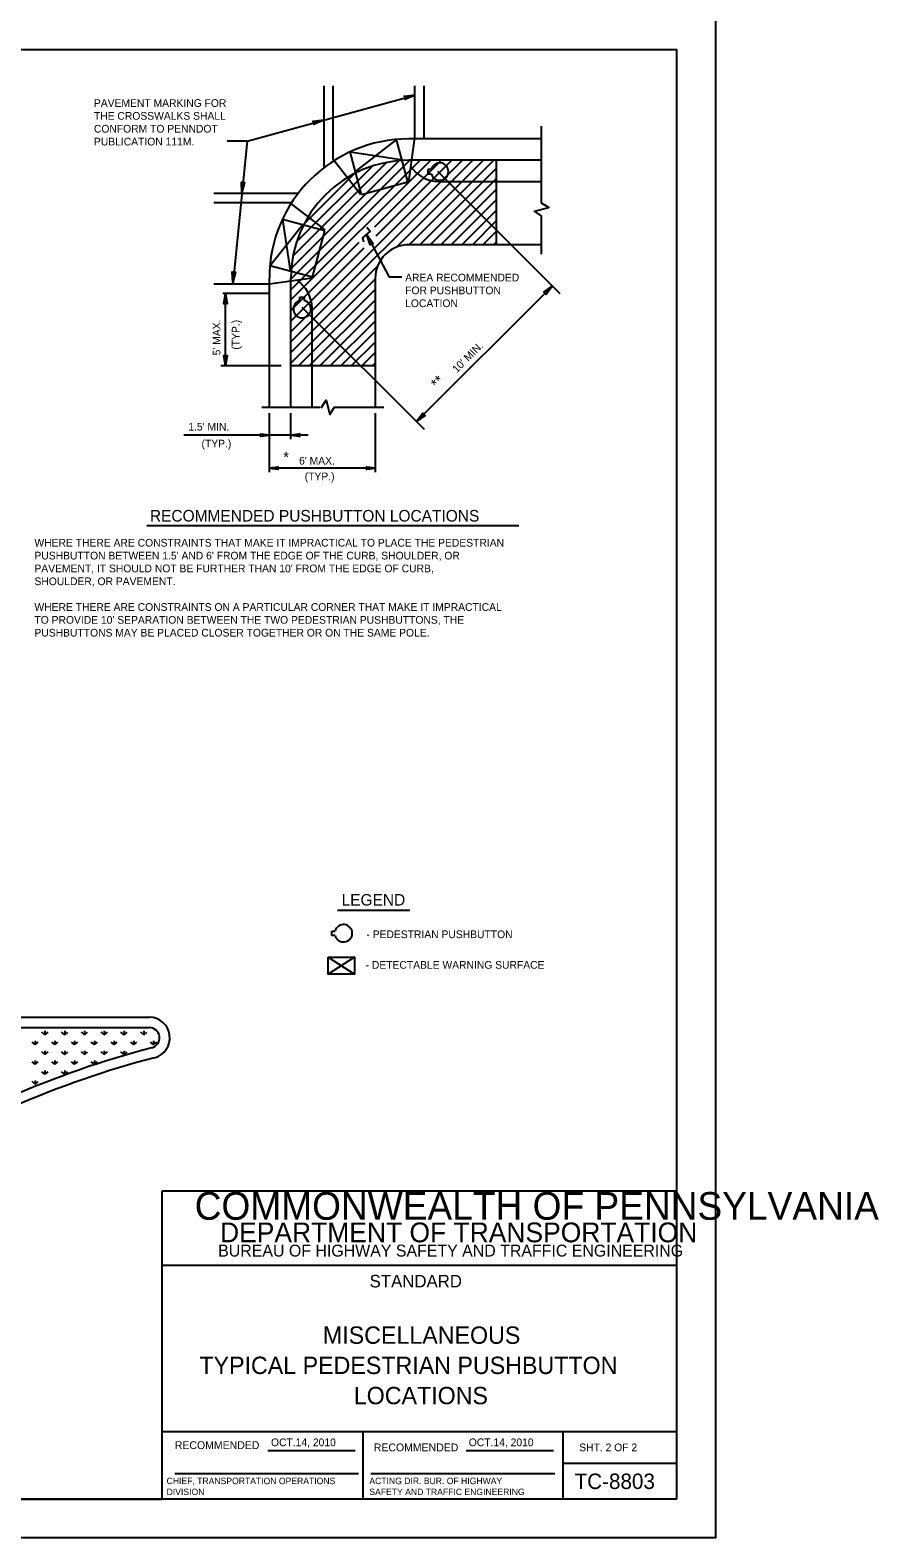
# Model space of a CAD drawing. Extents: x -344 to 940, y 22 to 1233.
# Drawn here: x 610 to 940, y 22 to 609 of the extents above; entities that cross this region are included whole.
import ezdxf

# ---------------------------------------------------------------- set-up
doc = ezdxf.new("R2010")
doc.units = 0
for name, color, linetype in [('1', 7, 'Continuous'), ('2', 7, 'Continuous'), ('4', 7, 'Continuous'), ('Default', 7, 'Continuous'), ('PLT-BNDY', 7, 'Continuous')]:
    doc.layers.add(name, color=color, linetype=linetype)

msp = doc.modelspace()

# ---------------------------------------------------------------- linework, layer by layer
at = {"layer": '1'}
for p, q in [((75.86, 601.17), (861.86, 601.17)), ((861.86, 37.17), (861.86, 601.17)), ((661.86, 37.17), (661.86, 157.17)), ((661.86, 157.17), (861.86, 157.17)), ((861.86, 128.17), (661.86, 128.17)), ((661.86, 63.55), (861.86, 63.55)), ((739.86, 63.55), (739.86, 37.17)), ((817.73, 37.17), (817.73, 63.55)), ((702.9, 56.2), (736.82, 56.2)), ((779.99, 56.2), (813.91, 56.2)), ((666.74, 47.21), (738.07, 47.21)), ((742.95, 47.21), (814.41, 47.21)), ((817.73, 51.17), (861.86, 51.17)), ((861.86, 37.17), (75.86, 37.17)), ((75.86, 37.17), (661.86, 37.17))]:
    msp.add_line(p, q, dxfattribs=at)
at = {"layer": '2'}
for p, q in [((724.73, 555.2), (724.73, 587)), ((728.34, 558.31), (728.34, 587)), ((760.03, 566.8), (760.03, 587)), ((763.64, 566.8), (763.64, 587)), ((694.86, 565.52), (760.03, 583.38)), ((809.33, 541.39), (809.33, 571.27)), ((694.86, 565.52), (687.02, 565.52)), ((694.86, 565.52), (689.22, 509.9)), ((752.88, 566.15), (736.76, 553.59)), ((757.31, 549.62), (752.88, 566.15)), ((757.68, 549.72), (760.03, 566.8)), ((809.33, 566.37), (757.68, 566.37)), ((711.63, 487.12), (782.74, 558.23)), ((711.66, 491.24), (778.63, 558.2)), ((711.76, 503.6), (766.27, 558.11)), ((711.79, 507.71), (762.15, 558.08)), ((711.82, 511.83), (758.03, 558.04)), ((712.03, 516.13), (753.78, 557.88)), ((712.6, 520.79), (749.03, 557.22)), ((738.92, 544.69), (728.34, 558.31)), ((739.29, 544.79), (734.86, 561.33)), ((734.86, 561.33), (754.56, 558.29)), ((744.42, 532.17), (770.39, 558.14)), ((745.03, 528.7), (774.51, 558.17)), ((752.85, 524.26), (786.86, 558.27)), ((809.33, 558.04), (757.68, 558.04)), ((757.87, 525.19), (790.98, 558.3)), ((791.76, 525.19), (791.76, 558.3)), ((714.05, 526.32), (743.67, 555.95)), ((716.59, 532.95), (736.66, 553.03)), ((761.96, 525.19), (791.76, 554.99)), ((765.12, 554.48), (765.12, 552.83)), ((766.42, 554.48), (765.12, 554.48)), ((765.12, 552.83), (766.42, 552.83)), ((816.56, 506.12), (769.02, 553.65)), ((739.29, 544.79), (757.31, 549.62)), ((766.05, 525.19), (791.76, 550.9)), ((809.33, 549.72), (769.2, 549.72)), ((770.13, 525.19), (791.76, 546.82)), ((714.67, 545.13), (681.91, 545.13)), ((711.55, 541.52), (681.91, 541.52)), ((725.18, 530.95), (711.55, 541.52)), ((774.22, 525.19), (791.76, 542.73)), ((725.08, 530.57), (708.54, 535.01)), ((708.54, 535.01), (711.6, 515.12)), ((778.31, 525.19), (791.76, 538.64)), ((782.4, 525.19), (791.76, 534.56)), ((809.33, 521.49), (809.33, 536.4)), ((703.71, 516.99), (716.3, 532.92)), ((720.25, 512.55), (725.08, 530.57)), ((741.37, 529.03), (750.03, 512.52)), ((786.48, 525.19), (791.76, 530.47)), ((711.69, 495.36), (740.38, 524.04)), ((711.73, 499.48), (738.44, 526.19)), ((809.33, 525.19), (757.68, 525.19)), ((790.57, 525.19), (791.76, 526.38)), ((720.25, 512.55), (703.71, 516.99)), ((711.6, 483), (745.49, 516.9)), ((720.15, 512.18), (703.5, 509.9)), ((703.5, 461.83), (703.5, 512.18)), ((711.57, 478.88), (744.68, 511.99)), ((711.82, 461.83), (711.82, 512.18)), ((744.68, 461.83), (744.68, 512.18)), ((755.01, 512.52), (750.03, 512.52)), ((703.5, 509.9), (681.91, 509.9)), ((703.5, 506.28), (685.41, 506.28)), ((686.44, 478.1), (686.44, 506.28)), ((714.87, 478.1), (744.68, 507.9)), ((715.38, 504.74), (717.04, 504.74)), ((715.38, 503.44), (715.38, 504.74)), ((717.04, 504.74), (717.04, 503.44)), ((760.67, 456.38), (813.49, 509.19)), ((763.75, 453.31), (716.21, 500.84)), ((718.96, 478.1), (744.68, 503.82)), ((720.15, 461.83), (720.15, 500.67)), ((723.05, 478.1), (744.68, 499.73)), ((727.14, 478.1), (744.68, 495.64)), ((731.22, 478.1), (744.68, 491.56)), ((735.31, 478.1), (744.68, 487.47)), ((739.4, 478.1), (744.68, 483.38)), ((708.02, 478.1), (684.68, 478.1)), ((744.68, 478.1), (711.56, 478.1)), ((743.48, 478.1), (744.68, 479.29)), ((723.06, 461.83), (700.5, 461.83)), ((703.5, 436.71), (703.5, 459.66)), ((711.82, 449.54), (711.82, 459.66)), ((747.95, 461.83), (728.5, 461.83)), ((744.68, 436.71), (744.68, 459.66)), ((703.5, 451.14), (670.18, 451.14)), ((711.82, 451.14), (703.5, 451.14)), ((718.58, 451.14), (711.82, 451.14)), ((744.68, 438.3), (703.5, 438.3)), ((800.5, 415.79), (655.84, 415.79)), ((758.08, 266.25), (730.01, 266.25)), ((727.72, 256.54), (727.72, 258.2)), ((727.72, 258.2), (729.02, 258.2)), ((729.02, 256.54), (727.72, 256.54)), ((726.35, 248.06), (736.6, 241.43)), ((736.6, 248.06), (726.35, 241.43))]:
    msp.add_line(p, q, dxfattribs=at)
for points in [[(756.18, 582.83), (756.39, 582.6), (760.03, 583.38), (756.18, 582.83), (755.94, 582.94), (760.03, 583.38), (756.5, 582.22), (756.44, 581.92), (760.03, 583.38), (756.29, 581.69), (756.44, 581.92)], [(720.64, 573.09), (720.85, 572.85), (724.49, 573.64), (720.64, 573.09), (720.4, 573.2), (724.49, 573.64), (720.96, 572.48), (720.9, 572.18), (724.49, 573.64), (720.74, 571.94), (720.9, 572.18)], [(693.7, 549.26), (693.4, 549.14), (692.82, 545.47), (693.7, 549.26), (693.88, 549.44), (692.82, 545.47), (693.02, 549.18), (692.76, 549.34), (692.82, 545.47), (692.59, 549.57), (692.76, 549.34)], [(809.43, 536.25), (806.51, 538.24), (812.08, 539.72), (809.3, 541.32)], [(741.43, 531.97), (742.72, 530.53), (739.67, 527.91), (740.05, 526.37)], [(742.73, 525.39), (742.91, 525.65), (741.37, 529.03), (742.73, 525.39), (742.67, 525.14), (741.37, 529.03), (743.25, 525.83), (743.56, 525.84), (741.37, 529.03), (743.82, 525.74), (743.56, 525.84)], [(690.17, 514.41), (689.87, 514.3), (689.3, 510.62), (690.17, 514.41), (690.35, 514.59), (689.3, 510.62), (689.49, 514.33), (689.23, 514.5), (689.3, 510.62), (689.06, 514.72), (689.23, 514.5)], [(685.95, 502.42), (686.23, 502.57), (686.44, 506.28), (685.95, 502.42), (685.78, 502.22), (686.44, 506.28), (686.62, 502.57), (686.9, 502.43), (686.44, 506.28), (687.08, 502.22), (686.9, 502.43)], [(810.41, 506.8), (810.71, 506.71), (813.49, 509.19), (810.41, 506.8), (810.15, 506.78), (813.49, 509.19), (810.99, 506.43), (811.09, 506.14), (813.49, 509.19), (811.07, 505.87), (811.09, 506.14)], [(686.92, 481.96), (686.64, 481.82), (686.44, 478.1), (686.92, 481.96), (687.09, 482.16), (686.44, 478.1), (686.25, 481.82), (685.98, 481.95), (686.44, 478.1), (685.79, 482.16), (685.98, 481.95)], [(723.56, 461.8), (725.54, 464.71), (727.03, 459.14), (728.63, 461.92)], [(763.75, 458.77), (763.45, 458.86), (760.67, 456.38), (763.75, 458.77), (764.01, 458.79), (760.67, 456.38), (763.17, 459.13), (763.07, 459.43), (760.67, 456.38), (763.09, 459.7), (763.07, 459.43)], [(700.22, 451.55), (700.34, 451.31), (703.5, 451.14), (700.22, 451.55), (700.05, 451.69), (703.5, 451.14), (700.34, 450.98), (700.23, 450.75), (703.5, 451.14), (700.05, 450.59), (700.23, 450.75)], [(715.1, 450.73), (714.98, 450.96), (711.82, 451.14), (715.1, 450.73), (715.27, 450.58), (711.82, 451.14), (714.98, 451.29), (715.09, 451.53), (711.82, 451.14), (715.27, 451.69), (715.09, 451.53)], [(706.78, 437.89), (706.66, 438.13), (703.5, 438.3), (706.78, 437.89), (706.95, 437.75), (703.5, 438.3), (706.65, 438.46), (706.77, 438.7), (703.5, 438.3), (706.95, 438.85), (706.77, 438.7)], [(741.39, 438.72), (741.52, 438.48), (744.68, 438.3), (741.39, 438.72), (741.23, 438.86), (744.68, 438.3), (741.52, 438.15), (741.4, 437.91), (744.68, 438.3), (741.23, 437.76), (741.4, 437.91)]]:
    msp.add_lwpolyline(points, dxfattribs=at)
msp.add_lwpolyline([(726.35, 248.06), (736.6, 248.06), (736.6, 241.43), (726.35, 241.43)], close=True, dxfattribs=at)
for centre, radius, start, end in [((757.68, 512.18), 54.19, 90, 180), ((757.68, 512.18), 45.86, 90, 180), ((769.79, 563.62), 13.9, 215.58755, 267.56335), ((769.71, 553.65), 3.4, 194.10136, 165.89864), ((757.68, 512.18), 13.01, 90, 180), ((706.24, 500.08), 13.9, 2.43665, 54.41245), ((716.21, 500.15), 3.4, 104.10136, 75.89864), ((732.31, 257.37), 3.4, 194.10136, 165.89864)]:
    msp.add_arc(centre, radius, start, end, dxfattribs=at)
at = {"layer": 'Default'}
for p, q in [((452.2, 224.68), (656.79, 224.68)), ((452.2, 220.68), (656.79, 220.68)), ((616.26, 217.9), (615.06, 218.86)), ((616.26, 219.34), (616.26, 217.9)), ((616.26, 217.9), (617.46, 218.86)), ((623.94, 217.9), (622.74, 218.86)), ((623.94, 219.34), (623.94, 217.9)), ((623.94, 217.9), (625.14, 218.86)), ((631.62, 217.9), (630.42, 218.86)), ((631.62, 219.34), (631.62, 217.9)), ((631.62, 217.9), (632.82, 218.86)), ((639.3, 217.9), (638.1, 218.86)), ((639.3, 219.34), (639.3, 217.9)), ((639.3, 217.9), (640.5, 218.86)), ((646.98, 217.9), (645.78, 218.86)), ((646.98, 219.34), (646.98, 217.9)), ((646.98, 217.9), (648.18, 218.86)), ((654.66, 217.9), (653.46, 218.86)), ((654.66, 219.34), (654.66, 217.9)), ((654.66, 217.9), (655.86, 218.86)), ((612.42, 214.06), (611.22, 215.02)), ((612.42, 215.5), (612.42, 214.06)), ((612.42, 214.06), (613.62, 215.02)), ((616.26, 210.22), (615.06, 211.18)), ((616.26, 211.66), (616.26, 210.22)), ((616.26, 210.22), (617.46, 211.18)), ((620.1, 214.06), (618.9, 215.02)), ((620.1, 215.5), (620.1, 214.06)), ((620.1, 214.06), (621.3, 215.02)), ((623.94, 210.22), (622.74, 211.18)), ((623.94, 211.66), (623.94, 210.22)), ((623.94, 210.22), (625.14, 211.18)), ((627.78, 214.06), (626.58, 215.02)), ((627.78, 215.5), (627.78, 214.06)), ((627.78, 214.06), (628.98, 215.02)), ((631.62, 210.22), (630.42, 211.18)), ((631.62, 211.66), (631.62, 210.22)), ((631.62, 210.22), (632.82, 211.18)), ((635.46, 214.06), (634.26, 215.02)), ((635.46, 215.5), (635.46, 214.06)), ((635.46, 214.06), (636.66, 215.02)), ((639.3, 210.22), (638.1, 211.18)), ((639.3, 211.66), (639.3, 210.22)), ((639.3, 210.22), (640.5, 211.18)), ((643.14, 214.06), (641.94, 215.02)), ((643.14, 215.5), (643.14, 214.06)), ((643.14, 214.06), (644.34, 215.02)), ((646.98, 210.22), (645.78, 211.18)), ((646.98, 211.66), (646.98, 210.22)), ((646.98, 210.22), (648.18, 211.18)), ((650.82, 214.06), (649.62, 215.02)), ((650.82, 215.5), (650.82, 214.06)), ((650.82, 214.06), (652.02, 215.02)), ((658.5, 214.06), (657.3, 215.02)), ((658.5, 215.5), (658.5, 214.06)), ((658.5, 214.06), (659.7, 215.02)), ((612.42, 206.38), (611.22, 207.34)), ((612.42, 207.82), (612.42, 206.38)), ((612.42, 206.38), (613.62, 207.34)), ((620.1, 206.38), (618.9, 207.34)), ((620.1, 207.82), (620.1, 206.38)), ((620.1, 206.38), (621.3, 207.34)), ((627.78, 206.38), (626.58, 207.34)), ((627.78, 207.82), (627.78, 206.38)), ((627.78, 206.38), (628.98, 207.34)), ((635.46, 206.38), (634.26, 207.34)), ((635.46, 207.82), (635.46, 206.38)), ((635.46, 206.38), (636.66, 207.34)), ((612.42, 198.7), (611.22, 199.66)), ((612.42, 200.14), (612.42, 198.7)), ((612.42, 198.7), (613.62, 199.66)), ((616.26, 202.54), (615.06, 203.5)), ((616.26, 203.98), (616.26, 202.54)), ((616.26, 202.54), (617.46, 203.5)), ((623.94, 202.54), (622.74, 203.5)), ((623.94, 203.98), (623.94, 202.54)), ((623.94, 202.54), (625.14, 203.5))]:
    msp.add_line(p, q, dxfattribs=at)
for centre, radius, start, end in [((656.79, 216.68), 8, 284.70628, 90), ((656.79, 216.68), 4, 284.70628, 90), ((753.46, -151.64), 376.8, 104.70628, 122.52612), ((753.46, -151.64), 372.8, 104.70628, 122.52612)]:
    msp.add_arc(centre, radius, start, end, dxfattribs=at)
at = {"layer": 'PLT-BNDY'}
msp.add_lwpolyline([(35.86, 616.17), (876.86, 616.17), (876.86, 22.17), (35.86, 22.17)], close=True, dxfattribs=at)

# ---------------------------------------------------------------- texts
at = {"layer": '1'}
for s, height, p in [('COMMONWEALTH OF PENNSYLVANIA', 10.7828, (674.45, 145.9)), ('DEPARTMENT OF TRANSPORTATION', 7.6837, (684.31, 137.15)), ('BUREAU OF HIGHWAY SAFETY AND TRAFFIC ENGINEERING', 4.6253, (683.58, 131.59)), ('MISCELLANEOUS', 6.75, (724.3, 97.65)), ('TYPICAL PEDESTRIAN PUSHBUTTON', 6.75, (676.28, 85.9)), ('LOCATIONS', 6.75, (736.3, 74.15)), ('RECOMMENDED', 3.0516, (666.73, 56.7)), ('OCT.14, 2010', 3, (704.12, 57.83)), ('RECOMMENDED', 3.0516, (744.08, 55.82)), ('SHT. 2 OF 2', 3, (823.94, 55.86)), ('TC-8803', 6, (822.14, 41.17))]:
    msp.add_text(s, height=height, dxfattribs=at).set_placement(p)
msp.add_text('OCT.14, 2010', height=3, rotation=360, dxfattribs=at).set_placement((781, 57.83))
at = {"layer": '2'}
for s, height, p in [('PAVEMENT MARKING FOR', 3.0001, (635.28, 578.82)), ('THE CROSSWALKS SHALL', 3.0001, (635.28, 573.82)), ('CONFORM TO PENNDOT', 3.0001, (635.28, 568.82)), ('PUBLICATION 111M.', 3.0001, (635.28, 563.82)), ('AREA RECOMMENDED', 3.0001, (756.27, 510.93)), ('FOR PUSHBUTTON', 3.0001, (756.27, 505.93)), ('LOCATION', 3, (756.27, 500.93)), ("1.5' MIN.", 3, (671.96, 452.91)), ('(TYP.)', 3, (677.11, 446.34)), ('*', 4.2, (708.9, 440.46)), ("6' MAX.", 3, (715.02, 439.68)), ('(TYP.)', 3, (717.23, 433.59)), ('RECOMMENDED PUSHBUTTON LOCATIONS', 4.5, (657.04, 417.52)), ('WHERE THERE ARE CONSTRAINTS THAT MAKE IT IMPRACTICAL TO PLACE THE PEDESTRIAN', 3, (612.16, 407.77)), ("PUSHBUTTON BETWEEN 1.5' AND 6' FROM THE EDGE OF THE CURB, SHOULDER, OR", 3, (612.16, 402.77)), ("PAVEMENT, IT SHOULD NOT BE FURTHER THAN 10' FROM THE EDGE OF CURB, ", 3, (612.16, 397.77)), ('SHOULDER, OR PAVEMENT.', 3, (612.16, 392.77)), ('WHERE THERE ARE CONSTRAINTS ON A PARTICULAR CORNER THAT MAKE IT IMPRACTICAL', 3, (612.16, 382.77)), ("TO PROVIDE 10' SEPARATION BETWEEN THE TWO PEDESTRIAN PUSHBUTTONS, THE ", 3, (612.16, 377.77)), ('PUSHBUTTONS MAY BE PLACED CLOSER TOGETHER OR ON THE SAME POLE.', 3, (612.16, 372.77)), ('LEGEND', 4.5, (731.56, 268.12)), ('- PEDESTRIAN PUSHBUTTON', 3, (741.2, 255.46)), ('- DETECTABLE WARNING SURFACE', 3, (740.89, 243.56))]:
    msp.add_text(s, height=height, dxfattribs=at).set_placement(p)
for s, height, rotation, p in [("5' MAX.", 3, 90, (684.47, 482.15)), ('(TYP.)', 3, 90, (691.88, 484.4)), ("10' MIN.", 3, 45, (776.36, 475.13)), ('**', 4.2, 45, (768.78, 468.78))]:
    msp.add_text(s, height=height, rotation=rotation, dxfattribs=at).set_placement(p)
at = {"layer": '4'}
msp.add_text('STANDARD', height=4.881, rotation=360, dxfattribs=at).set_placement((742.45, 119.59))
at = {"layer": 'Default'}
for s, p in [('CHIEF, TRANSPORTATION OPERATIONS', (663.54, 43.06)), ('DIVISION', (663.54, 38.81)), ('ACTING DIR. BUR. OF HIGHWAY', (742.35, 43.06)), ('SAFETY AND TRAFFIC ENGINEERING', (742.35, 38.81))]:
    msp.add_text(s, height=2.5, dxfattribs=at).set_placement(p)

doc.saveas('drawing.dxf')
